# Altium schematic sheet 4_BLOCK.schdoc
size 302 x 215 mm; Symbol: Sheet_A4; Device: Sheet_A4; @Project Name: Yuzukilizard; REV: 1.0; Date: 2022-10-08; Sheet: 1/1; Draw By: GloomyGhost; Company: YuzukiHD
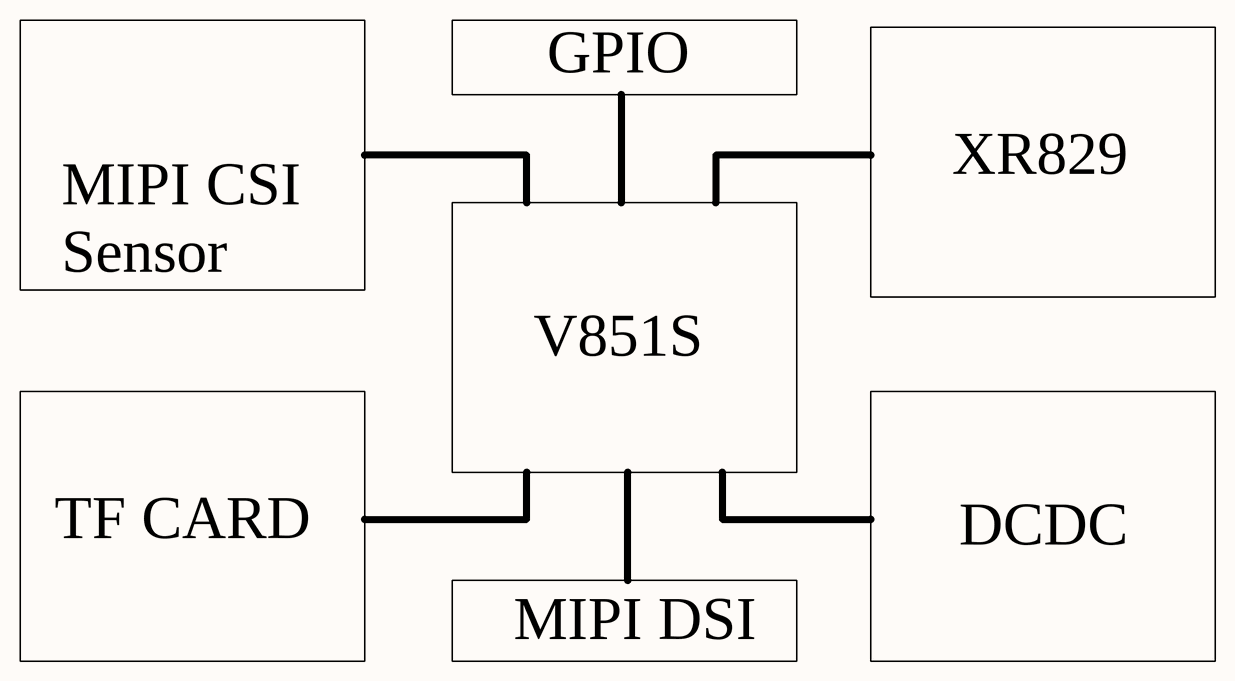
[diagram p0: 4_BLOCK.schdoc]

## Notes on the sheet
- GPIO
- MIPI CSI
  Sensor
- XR829
- V851S
- TF CARD
- DCDC
- MIPI DSI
